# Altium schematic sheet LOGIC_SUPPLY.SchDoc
size A4; SheetNumber: 13; SheetTotal: 17
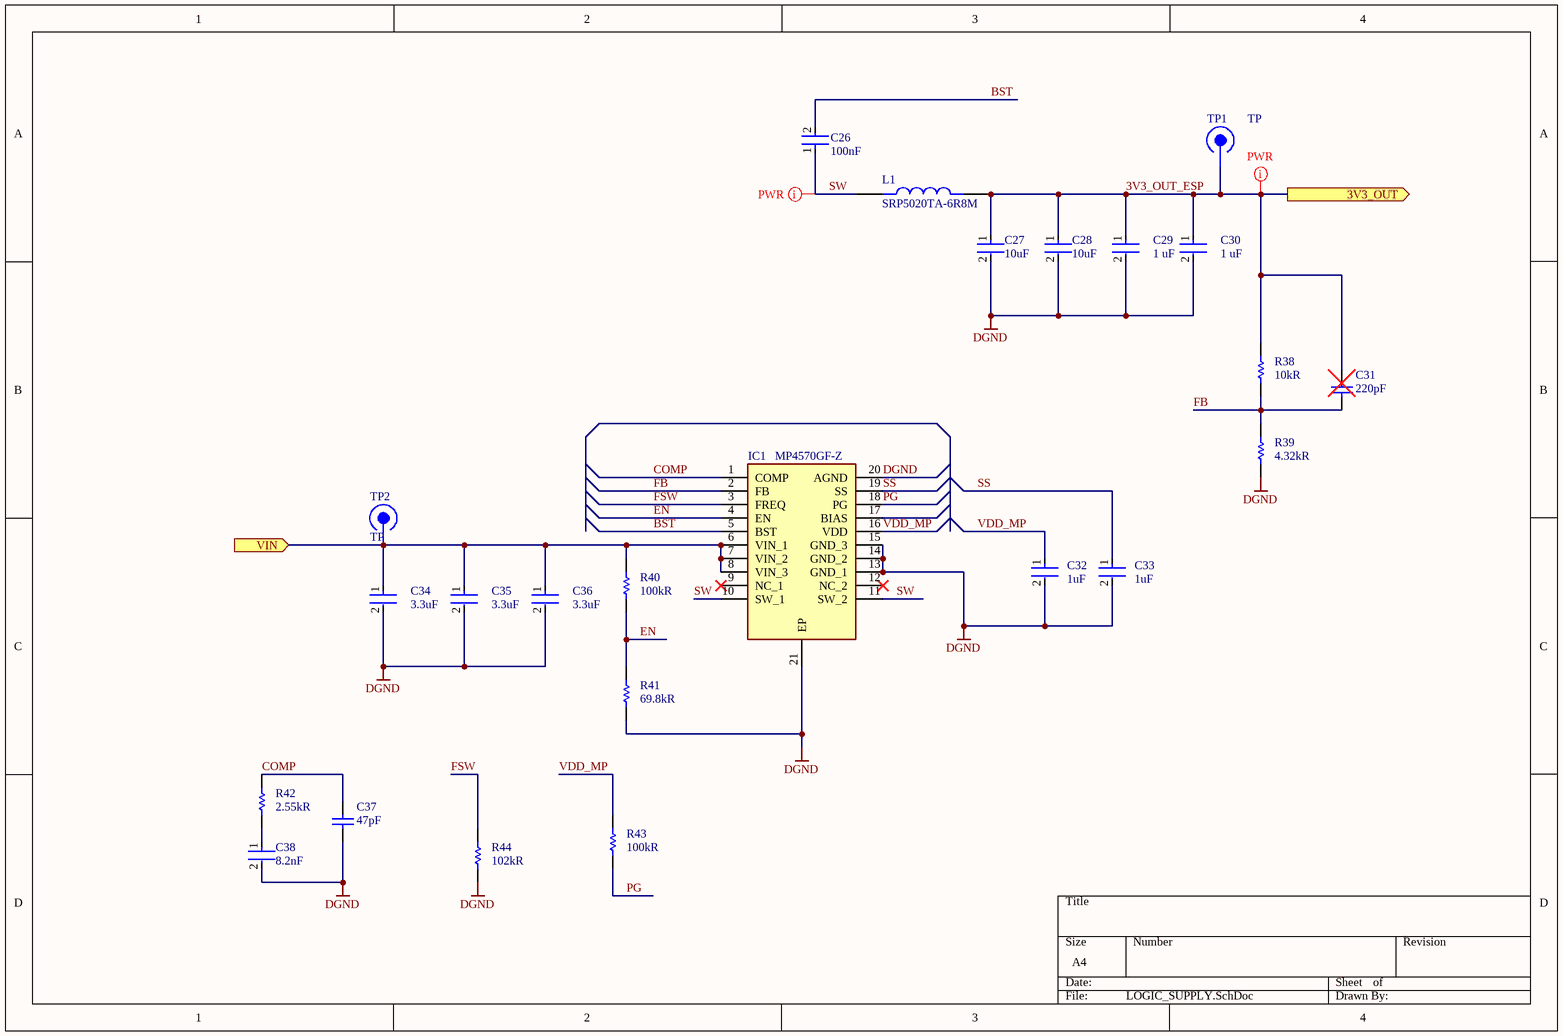
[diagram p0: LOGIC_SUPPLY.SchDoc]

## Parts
C26  value 100nF  [FP-CC0402-IPC_B]  (hidden comment: CC0402KRX7R9BB104)
C27  value 10uF  [FP-GRM21B-0_15-MFG]  (hidden comment: GRM21BR71A106KA73L)
C28  value 10uF  [FP-GRM21B-0_15-MFG]  (hidden comment: GRM21BR71A106KA73L)
C29  value 1 uF  [FP-CC0402-MFG]  (hidden comment: CC0402KRX5R6BB105)
C30  value 1 uF  [FP-CC0402-MFG]  (hidden comment: CC0402KRX5R6BB105)
C31  value 220pF  [CAPC1005X55X25LL05T10]  (hidden comment: GRM1555C1H221GA01J)  (no BOM)
C32  Capacitance: 1uF  [FP-GRM155-0_05-IPC_B]  (hidden comment: GRM155R61E105KA12D)
C33  Capacitance: 1uF  [FP-GRM155-0_05-IPC_B]  (hidden comment: GRM155R61E105KA12D)
C34  value 3.3uF  [FP-C2012-125-0_2-MFG]  (hidden comment: C2012X7R1E335K125AB)
C35  value 3.3uF  [FP-C2012-125-0_2-MFG]  (hidden comment: C2012X7R1E335K125AB)
C36  value 3.3uF  [FP-C2012-125-0_2-MFG]  (hidden comment: C2012X7R1E335K125AB)
C37  value 47pF  [CAPC1005X55X25LL05T10]  (hidden comment: GRM1555C1H470GA01D)
C38  value 8.2nF  [FP-GRM155-0_15-IPC_C]  (hidden comment: GRM1555C1H822JE01D)
IC1  MP4570GF-Z  [MP4570GF-Z-Footprint-1]
L1  SRP5020TA-6R8M  [SRP5020TA-6R8M-Footprint-1]
R38  value 10kR  [RESC1005X40X25LL10T10]  (hidden comment: RK73H1ETTP1002F)
R39  value 4.32kR  [RESC1005X40X25LL10T10]  (hidden comment: RK73H1ETTP4321F)
R40  value 100kR  [RESC1005X40X25NL10T10]  (hidden comment: RK73H1ETTP1003F)
R41  value 69.8kR  [RESC1005X40X25NL10T10]  (hidden comment: RK73H1ETTP6982F)
R42  value 2.55kR  [RESC1005X40X25ML10T10]  (hidden comment: RK73H1ETTP2551F)
R43  value 100kR  [RESC1005X40X25LL10T10]  (hidden comment: RK73H1ETTP1003F)
R44  value 102kR  [RESC1005X40X25ML10T10]  (hidden comment: RK73H1ETTP1023F)
TP1  TP  [TP-Footprint-1]
TP2  TP  [TP-Footprint-1]

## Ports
3V3_OUT (out), VIN (in)

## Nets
DGND: C27.2 C28.2 C29.2 C30.2 C32.2 C33.2 C34.2 C35.2 C36.2 C37.1 C38.2 IC1.13(GND_1) IC1.14(GND_2) IC1.15(GND_3) IC1.20(AGND) IC1.21(EP) R39.1 R41.1 R44.1
3V3_OUT_ESP: C27.1 C28.1 C29.1 C30.1 C31.2 L1.2 R38.2 TP1.1 ; port 3V3_OUT
BST: C26.2 IC1.5(BST)
COMP: C37.2 IC1.1(COMP) R42.2
EN: IC1.4(EN) R40.1 R41.2
FB: C31.1 IC1.2(FB) R38.1 R39.2
FSW: IC1.3(FREQ) R44.2
PG: IC1.18(PG) R43.1
SS: C33.1 IC1.19(SS)
SW: C26.1 IC1.10(SW_1) IC1.11(SW_2) L1.1
VDD_MP: C32.1 IC1.16(VDD) R43.2
VIN: C34.1 C35.1 C36.1 IC1.6(VIN_1) IC1.7(VIN_2) IC1.8(VIN_3) R40.2 TP2.1 ; port VIN
NetC38_1: C38.1 R42.1

Not connected (* = marked no-connect by the designer): IC1 9(NC_1)* 12(NC_2)* 17(BIAS)

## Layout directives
net class PWR: 3V3_OUT_ESP, SW

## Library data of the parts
C26 = CMP-x00152-1: Ceramic Capacitor, Multilayer, Ceramic, 50V, 10% +Tol, 10% -Tol, X7R, 15% TC, 0.1uF, Surface Mount, 0402
C27 C28 = CMP-x00157-1: Ceramic Capacitor, Multilayer, Ceramic, 10V, 10% +Tol, 10% -Tol, X7R, 15% TC, 10uF, Surface Mount, 0805
C29 C30 = CMP-03422-000489-1: CAP CER 1UF 10V X5R 0402; Manufacturer: YAGEO; Temperature Coefficient: 30ppm/°C; Tolerance: 0.1; Automotive Grade: NA; Material: Ceramic
C31 = CMP-2008-04169-1: Manufacturer: Murata
C32 C33 = CMP-2008-04581-2: Chip Multilayer Ceramic Capacitors for General Purpose, 0402, 1.0uF, X5R, 15%, 10%, 25V
C34-C36 = CMP-08246-006023-1: Multilayer Ceramic Capacitors 3.3μF ±10% 25V X7R SMD 0805
C37 = CMP-2008-04366-1: Manufacturer: Murata
C38 = CMP-06035-016894-1: Chip Multilayer Ceramic Capacitors for General Purpose, 0402, 8200pF, C0G, 30ppm/°C, 5%, 50V
IC1 = CMP-001-0077-1: Switching Voltage Regulators 3A,4.5V-55V Input, Freqcy Programmable; Vendor: Mouser
L1 = CMP-x00175-1: General Purpose Inductor, 6.8uH, 20%, 1 Element, Metal Alloy Powder-Core, SMD, 2220
R38 = CMP-x00150-1: Fixed Resistor, Metal Glaze/thick Film, 0.1W, 10000ohm, 75V, 1% +/-Tol, 100ppm/Cel, Surface Mount, 0402
R39 = CMP-2002-04376-1: Part Number: RK73H1ETTP33R2F; Manufacturer: KOA Speer
R40 R43 = CMP-x00162-1: Fixed Resistor, Metal Glaze/thick Film, 0.1W, 100000ohm, 75V, 1% +/-Tol, 100ppm/Cel, Surface Mount, 0402
R41 = CMP-2002-04506-1: Manufacturer: KOA Speer
R42 = CMP-2002-04318-1: Manufacturer: KOA Speer
R44 = CMP-2002-04177-1: Manufacturer: KOA Speer
TP1 TP2 = CMP-001-0086-3: digital shovel test point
